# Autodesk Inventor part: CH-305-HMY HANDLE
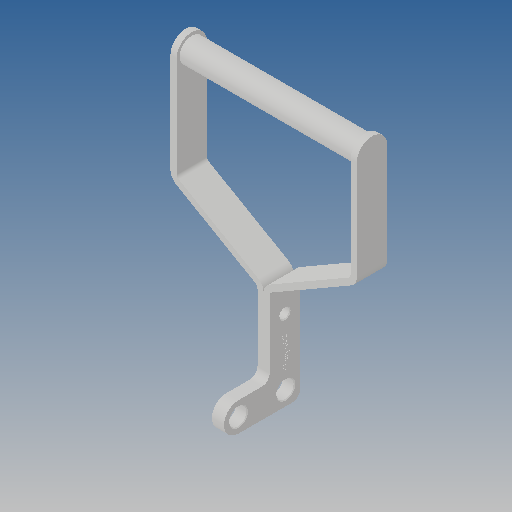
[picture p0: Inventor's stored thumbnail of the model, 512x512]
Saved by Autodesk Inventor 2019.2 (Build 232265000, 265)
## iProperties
Created: 2015-08
Part Number: CH-305-HMY HANDLE
Material: Ogólny
Document SubType Name: Modeling
Designer: CADENGINEERING4
Density: 1 g/cm^3
Appearance: Domyślna
Author: CADENGINEERING4
Revision Number: ÈÎºÎ
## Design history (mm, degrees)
feature "ÇÐ³ý-À­Éì2"
node "Bryła1"
